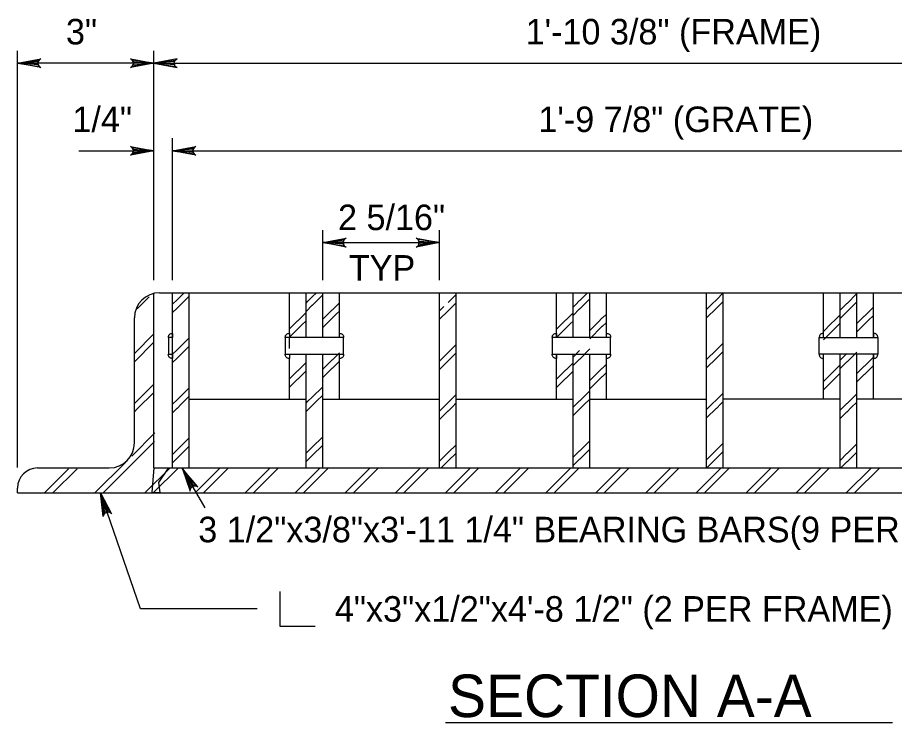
# Model space of a CAD drawing. Extents: x 0.71 to 8.05, y -5.67 to 4.31.
# Drawn here: x 0.92 to 2.981, y -1.711 to -0.055 of the extents above; entities that cross this region are included whole.
import ezdxf

# ---------------------------------------------------------------- set-up
doc = ezdxf.new("R2010")
doc.units = 0
for name, color, linetype in [('DETL-DIMS', 7, 'Continuous'), ('DETL-LINE', 7, 'Continuous'), ('DETL-NOTE', 7, 'Continuous'), ('DETL-PATT', 7, 'Continuous'), ('DETL-TITL', 7, 'Continuous')]:
    doc.layers.add(name, color=color, linetype=linetype)

msp = doc.modelspace()

# ---------------------------------------------------------------- linework, layer by layer
at = {"layer": 'DETL-DIMS'}
for p, q in [((0.9201, -1.1122), (0.9201, -0.1331)), ((1.2402, -0.6723), (1.2402, -0.1331)), ((1.2402, -0.1625), (0.9201, -0.1625)), ((1.2402, -0.1625), (3.8775, -0.1625)), ((1.2844, -0.6723), (1.2844, -0.339)), ((1.0638, -0.3684), (1.2402, -0.3684)), ((1.2844, -0.3684), (3.8334, -0.3684)), ((1.6373, -0.6723), (1.6373, -0.5547)), ((1.9118, -0.6723), (1.9118, -0.5547)), ((1.6373, -0.5841), (1.9118, -0.5841)), ((1.3608, -1.2069), (1.3075, -1.1153)), ((1.2087, -1.4447), (1.1148, -1.1723)), ((1.4828, -1.4447), (1.2087, -1.4447))]:
    msp.add_line(p, q, dxfattribs=at)
for points in [[(0.9201, -0.1625), (0.975, -0.1522), (0.9707, -0.1552), (0.9686, -0.1588), (0.9679, -0.1625), (0.9686, -0.1662), (0.9707, -0.1699), (0.975, -0.1728), (0.9201, -0.1625), (0.9707, -0.1699), (0.9686, -0.1662), (0.9201, -0.1625), (0.9679, -0.1625), (0.9686, -0.1588), (0.9201, -0.1625), (0.9707, -0.1552)], [(1.2402, -0.1625), (1.1854, -0.1728), (1.1896, -0.1699), (1.1918, -0.1662), (1.1924, -0.1625), (1.1918, -0.1588), (1.1896, -0.1552), (1.1854, -0.1522), (1.2402, -0.1625), (1.1896, -0.1552), (1.1918, -0.1588), (1.2402, -0.1625), (1.1924, -0.1625), (1.1918, -0.1662), (1.2402, -0.1625), (1.1896, -0.1699)], [(1.2402, -0.1625), (1.2951, -0.1728), (1.2908, -0.1699), (1.2887, -0.1662), (1.288, -0.1625), (1.2887, -0.1588), (1.2908, -0.1552), (1.2951, -0.1522), (1.2402, -0.1625), (1.2908, -0.1552), (1.2887, -0.1588), (1.2402, -0.1625), (1.288, -0.1625), (1.2887, -0.1662), (1.2402, -0.1625), (1.2908, -0.1699)], [(1.2402, -0.3684), (1.1854, -0.3787), (1.1896, -0.3758), (1.1918, -0.3721), (1.1924, -0.3684), (1.1918, -0.3647), (1.1896, -0.3611), (1.1854, -0.3581), (1.2402, -0.3684), (1.1896, -0.3611), (1.1918, -0.3647), (1.2402, -0.3684), (1.1924, -0.3684), (1.1918, -0.3721), (1.2402, -0.3684), (1.1896, -0.3758)], [(1.2844, -0.3684), (1.3392, -0.3581), (1.335, -0.3611), (1.3328, -0.3647), (1.3322, -0.3684), (1.3328, -0.3721), (1.335, -0.3758), (1.3392, -0.3787), (1.2844, -0.3684), (1.335, -0.3758), (1.3328, -0.3721), (1.2844, -0.3684), (1.3322, -0.3684), (1.3328, -0.3647), (1.2844, -0.3684), (1.335, -0.3611)], [(1.6373, -0.5841), (1.6921, -0.5738), (1.6879, -0.5767), (1.6857, -0.5804), (1.6851, -0.5841), (1.6857, -0.5878), (1.6879, -0.5914), (1.6921, -0.5944), (1.6373, -0.5841), (1.6879, -0.5914), (1.6857, -0.5878), (1.6373, -0.5841), (1.6851, -0.5841), (1.6857, -0.5804), (1.6373, -0.5841), (1.6879, -0.5767)], [(1.9118, -0.5841), (1.857, -0.5944), (1.8612, -0.5914), (1.8634, -0.5878), (1.864, -0.5841), (1.8634, -0.5804), (1.8612, -0.5767), (1.857, -0.5738), (1.9118, -0.5841), (1.8612, -0.5767), (1.8634, -0.5804), (1.9118, -0.5841), (1.864, -0.5841), (1.8634, -0.5878), (1.9118, -0.5841), (1.8612, -0.5914)], [(1.3075, -1.1153), (1.3257, -1.168), (1.3262, -1.1629), (1.3283, -1.1591), (1.3312, -1.1568), (1.3347, -1.1555), (1.3389, -1.1556), (1.3436, -1.1578), (1.3075, -1.1153), (1.3389, -1.1556), (1.3347, -1.1555), (1.3075, -1.1153), (1.3312, -1.1568), (1.3283, -1.1591), (1.3075, -1.1153), (1.3262, -1.1629)], [(1.1148, -1.1723), (1.1413, -1.2214), (1.1373, -1.2183), (1.1331, -1.2173), (1.1294, -1.2178), (1.1261, -1.2196), (1.1232, -1.2228), (1.1217, -1.2277), (1.1148, -1.1723), (1.1232, -1.2228), (1.1261, -1.2196), (1.1148, -1.1723), (1.1294, -1.2178), (1.1331, -1.2173), (1.1148, -1.1723), (1.1373, -1.2183)]]:
    msp.add_lwpolyline(points, dxfattribs=at)
at = {"layer": 'DETL-LINE'}
for p, q in [((1.2402, -1.1135), (1.2402, -0.7017)), ((1.2535, -0.7017), (3.8643, -0.7017)), ((1.2844, -1.1135), (1.2844, -0.7017)), ((1.3236, -1.1135), (1.3236, -0.7017)), ((1.5589, -0.7974), (1.5589, -0.7017)), ((1.5981, -0.8071), (1.5981, -0.7017)), ((1.6373, -0.8071), (1.6373, -0.7017)), ((1.6765, -0.7971), (1.6765, -0.7017)), ((1.9118, -1.1135), (1.9118, -0.7017)), ((1.951, -1.1135), (1.951, -0.7017)), ((2.1863, -0.8071), (2.1863, -0.7017)), ((2.2255, -0.8071), (2.2255, -0.7017)), ((2.2648, -0.8071), (2.2648, -0.7017)), ((2.304, -0.8071), (2.304, -0.7017)), ((2.5393, -1.1135), (2.5393, -0.7017)), ((2.5785, -1.1135), (2.5785, -0.7017)), ((2.8138, -0.8071), (2.8138, -0.7017)), ((2.853, -0.8071), (2.853, -0.7017)), ((2.8922, -0.8071), (2.8922, -0.7017)), ((2.9314, -0.8071), (2.9314, -0.7017)), ((1.1947, -1.0547), (1.1947, -0.7606)), ((1.5589, -0.8326), (1.5589, -0.8071)), ((1.5589, -0.9517), (1.5589, -0.8562)), ((1.5981, -1.1135), (1.5981, -0.8463)), ((1.6373, -1.1135), (1.6373, -0.8463)), ((1.6765, -0.9517), (1.6765, -0.8561)), ((2.1863, -0.9517), (2.1863, -0.8463)), ((2.2255, -1.1135), (2.2255, -0.8463)), ((2.2648, -1.1135), (2.2648, -0.8463)), ((2.304, -0.9517), (2.304, -0.8463)), ((2.8138, -0.9517), (2.8138, -0.8463)), ((2.853, -1.1135), (2.853, -0.8463)), ((2.8922, -1.1135), (2.8922, -0.8463)), ((2.9314, -0.9517), (2.9314, -0.8463)), ((1.3236, -0.9517), (1.5981, -0.9517)), ((1.6373, -0.9517), (1.9118, -0.9517)), ((1.951, -0.9517), (2.2255, -0.9517)), ((2.2648, -0.9517), (2.5393, -0.9517)), ((2.853, -0.9517), (2.5785, -0.9517)), ((3.1667, -0.9517), (2.8922, -0.9517)), ((0.9672, -1.1135), (1.1358, -1.1135)), ((1.2402, -1.1135), (3.8775, -1.1135)), ((0.9201, -1.1723), (0.9201, -1.1606)), ((0.9201, -1.1723), (3.9819, -1.1723))]:
    msp.add_line(p, q, dxfattribs=at)
for points in [[(1.2745, -0.8071), (1.2745, -0.8054), (1.2748, -0.8037), (1.2753, -0.8024), (1.2758, -0.8014), (1.2766, -0.8004), (1.2774, -0.7996), (1.2788, -0.7986), (1.2805, -0.7977), (1.2818, -0.7974), (1.2831, -0.7972), (1.2843, -0.7973), (1.2843, -0.8071)], [(1.5491, -0.8071), (1.5491, -0.8055), (1.5494, -0.8037), (1.5499, -0.8024), (1.5505, -0.8015), (1.5512, -0.8005), (1.552, -0.7996), (1.5534, -0.7986), (1.5551, -0.7978), (1.5564, -0.7975), (1.5577, -0.7973), (1.5589, -0.7974), (1.5589, -0.8071)], [(1.6765, -0.7973), (1.6782, -0.7974), (1.6799, -0.7977), (1.6812, -0.7982), (1.6822, -0.7987), (1.6832, -0.7995), (1.684, -0.8003), (1.685, -0.8017), (1.6859, -0.8033), (1.6862, -0.8047), (1.6864, -0.806), (1.6863, -0.8071), (1.6765, -0.8071)], [(2.1765, -0.8071), (2.1766, -0.8055), (2.1768, -0.8037), (2.1774, -0.8024), (2.1779, -0.8015), (2.1787, -0.8005), (2.1795, -0.7996), (2.1808, -0.7986), (2.1825, -0.7978), (2.1839, -0.7975), (2.1852, -0.7973), (2.1863, -0.7974), (2.1863, -0.8071)], [(2.304, -0.7973), (2.3056, -0.7974), (2.3074, -0.7977), (2.3087, -0.7982), (2.3096, -0.7987), (2.3106, -0.7995), (2.3115, -0.8003), (2.3125, -0.8017), (2.3133, -0.8033), (2.3136, -0.8047), (2.3138, -0.806), (2.3137, -0.8071), (2.304, -0.8071)], [(2.8138, -0.7973), (2.8121, -0.7974), (2.8104, -0.7977), (2.8091, -0.7982), (2.8081, -0.7987), (2.8071, -0.7995), (2.8063, -0.8003), (2.8053, -0.8017), (2.8044, -0.8033), (2.8041, -0.8047), (2.8039, -0.806), (2.804, -0.8071), (2.8138, -0.8071)], [(2.9412, -0.8071), (2.9412, -0.8055), (2.9409, -0.8037), (2.9404, -0.8024), (2.9398, -0.8015), (2.939, -0.8005), (2.9383, -0.7996), (2.9369, -0.7986), (2.9352, -0.7978), (2.9339, -0.7975), (2.9326, -0.7973), (2.9314, -0.7974), (2.9314, -0.8071)], [(1.2745, -0.8463), (1.2843, -0.8463), (1.2843, -0.8071), (1.2745, -0.8071)], [(1.5491, -0.8463), (1.6863, -0.8463), (1.6863, -0.8071), (1.5491, -0.8071)], [(2.1766, -0.8463), (2.3137, -0.8463), (2.3137, -0.8071), (2.1766, -0.8071)], [(2.9412, -0.8463), (2.804, -0.8463), (2.804, -0.8071), (2.9412, -0.8071)], [(1.2843, -0.8561), (1.2826, -0.8561), (1.2809, -0.8558), (1.2796, -0.8552), (1.2786, -0.8547), (1.2776, -0.8539), (1.2768, -0.8532), (1.2758, -0.8518), (1.2749, -0.8501), (1.2746, -0.8487), (1.2744, -0.8474), (1.2745, -0.8463), (1.2843, -0.8463)], [(1.5589, -0.8562), (1.5572, -0.8561), (1.5555, -0.8558), (1.5542, -0.8553), (1.5532, -0.8548), (1.5522, -0.854), (1.5514, -0.8532), (1.5504, -0.8518), (1.5495, -0.8501), (1.5492, -0.8488), (1.549, -0.8475), (1.5491, -0.8463), (1.5589, -0.8463)], [(1.6863, -0.8463), (1.6863, -0.848), (1.686, -0.8497), (1.6855, -0.8511), (1.6849, -0.852), (1.6841, -0.853), (1.6834, -0.8538), (1.682, -0.8549), (1.6803, -0.8557), (1.6789, -0.856), (1.6777, -0.8562), (1.6765, -0.8561), (1.6765, -0.8463)], [(2.1863, -0.8562), (2.1847, -0.8561), (2.1829, -0.8558), (2.1816, -0.8553), (2.1807, -0.8548), (2.1797, -0.854), (2.1788, -0.8532), (2.1778, -0.8518), (2.177, -0.8501), (2.1767, -0.8488), (2.1765, -0.8475), (2.1766, -0.8463), (2.1863, -0.8463)], [(2.3138, -0.8463), (2.3137, -0.848), (2.3134, -0.8497), (2.3129, -0.8511), (2.3124, -0.852), (2.3116, -0.853), (2.3108, -0.8538), (2.3094, -0.8549), (2.3078, -0.8557), (2.3064, -0.856), (2.3051, -0.8562), (2.304, -0.8561), (2.304, -0.8463)], [(2.804, -0.8463), (2.804, -0.848), (2.8043, -0.8497), (2.8048, -0.8511), (2.8054, -0.852), (2.8062, -0.853), (2.8069, -0.8538), (2.8083, -0.8549), (2.81, -0.8557), (2.8113, -0.856), (2.8126, -0.8562), (2.8138, -0.8561), (2.8138, -0.8463)], [(2.9314, -0.8562), (2.9331, -0.8561), (2.9348, -0.8558), (2.9361, -0.8553), (2.9371, -0.8548), (2.9381, -0.854), (2.9389, -0.8532), (2.9399, -0.8518), (2.9408, -0.8501), (2.9411, -0.8488), (2.9413, -0.8475), (2.9412, -0.8463), (2.9314, -0.8463)], [(1.2402, -1.1135), (1.2357, -1.1713), (1.2551, -1.1713), (1.2525, -1.1473), (1.2745, -1.1141)]]:
    msp.add_lwpolyline(points, close=True, dxfattribs=at)
for centre, radius, start, end in [((1.2535, -0.7606), 0.0588, 90, 180), ((1.1358, -1.0547), 0.0588, 270, 0), ((0.9672, -1.1606), 0.0471, 90, 180)]:
    msp.add_arc(centre, radius, start, end, dxfattribs=at)
at = {"layer": 'DETL-NOTE'}
for p, q in [((1.5373, -1.486), (1.5373, -1.4037)), ((1.6197, -1.486), (1.5373, -1.486))]:
    msp.add_line(p, q, dxfattribs=at)
at = {"layer": 'DETL-PATT'}
for p, q in [((1.2013, -0.7396), (1.2295, -0.7113)), ((1.2852, -0.728), (1.295, -0.7182)), ((1.2954, -0.7182), (1.3118, -0.7017)), ((1.3052, -0.728), (1.3236, -0.7096)), ((1.6025, -0.7215), (1.6123, -0.7117)), ((1.6128, -0.7117), (1.6228, -0.7017)), ((1.6226, -0.7215), (1.6373, -0.7068)), ((1.9323, -0.7246), (1.951, -0.7058)), ((2.2308, -0.7301), (2.2406, -0.7203)), ((2.2411, -0.7203), (2.2596, -0.7017)), ((2.2509, -0.7301), (2.2648, -0.7162)), ((2.5525, -0.728), (2.5623, -0.7182)), ((2.5627, -0.7182), (2.5785, -0.7024)), ((2.8693, -0.7267), (2.8922, -0.7039)), ((1.2844, -0.7484), (1.295, -0.7378)), ((1.3052, -0.728), (1.295, -0.7382)), ((1.5981, -0.726), (1.6025, -0.7215)), ((1.5981, -0.7456), (1.6123, -0.7313)), ((1.6226, -0.7215), (1.6123, -0.7318)), ((1.6497, -0.7516), (1.6595, -0.7418)), ((1.66, -0.7418), (1.6765, -0.7252)), ((1.9118, -0.7446), (1.922, -0.7344)), ((1.9421, -0.7344), (1.9318, -0.7446)), ((1.9421, -0.7344), (1.951, -0.7254)), ((2.2255, -0.7354), (2.2308, -0.7301)), ((2.2255, -0.755), (2.2406, -0.7399)), ((2.2509, -0.7301), (2.2406, -0.7403)), ((2.5393, -0.7412), (2.5525, -0.728)), ((2.5393, -0.7608), (2.5623, -0.7378)), ((2.5725, -0.728), (2.5623, -0.7382)), ((2.5725, -0.728), (2.5785, -0.722)), ((2.853, -0.7427), (2.8591, -0.7365)), ((2.8591, -0.7365), (2.8689, -0.7267)), ((2.8791, -0.7365), (2.8689, -0.7468)), ((2.8791, -0.7365), (2.8922, -0.7235)), ((2.9101, -0.7568), (2.9314, -0.7354)), ((1.5785, -0.7675), (1.5981, -0.7479)), ((1.6373, -0.764), (1.6497, -0.7516)), ((1.6373, -0.7836), (1.6595, -0.7614)), ((1.6698, -0.7516), (1.6595, -0.7618)), ((1.6698, -0.7516), (1.6765, -0.7448)), ((1.9118, -0.7642), (1.9318, -0.7442)), ((2.2089, -0.7654), (2.2255, -0.7487)), ((2.2844, -0.7709), (2.2942, -0.7611)), ((2.2947, -0.7611), (2.304, -0.7518)), ((2.8415, -0.7654), (2.853, -0.7538)), ((2.853, -0.7623), (2.8689, -0.7463)), ((2.8999, -0.7666), (2.9097, -0.7568)), ((2.9199, -0.7666), (2.9314, -0.755)), ((1.5589, -0.7867), (1.5682, -0.7773)), ((1.5682, -0.7773), (1.578, -0.7675)), ((1.5883, -0.7773), (1.578, -0.7875)), ((1.5883, -0.7773), (1.5981, -0.7675)), ((2.1863, -0.7875), (2.1987, -0.7752)), ((2.1987, -0.7752), (2.2085, -0.7654)), ((2.2187, -0.7752), (2.2085, -0.7854)), ((2.2187, -0.7752), (2.2255, -0.7683)), ((2.2648, -0.7905), (2.2844, -0.7709)), ((2.2648, -0.8102), (2.2942, -0.7807)), ((2.304, -0.7714), (2.2942, -0.7811)), ((2.8138, -0.7926), (2.8312, -0.7752)), ((2.8312, -0.7752), (2.841, -0.7654)), ((2.8513, -0.7752), (2.841, -0.7854)), ((2.8922, -0.7742), (2.8999, -0.7666)), ((2.8922, -0.7938), (2.9097, -0.7764)), ((2.9199, -0.7666), (2.9097, -0.7768)), ((1.1947, -0.8443), (1.2402, -0.7987)), ((1.5589, -0.8063), (1.578, -0.7871)), ((2.1863, -0.8071), (2.2085, -0.785)), ((2.8138, -0.8122), (2.841, -0.785)), ((1.1947, -0.8639), (1.2402, -0.8183)), ((1.2954, -0.8358), (1.3236, -0.8076)), ((1.9323, -0.8422), (1.951, -0.8235)), ((2.5627, -0.8358), (2.5785, -0.82)), ((1.2844, -0.8464), (1.295, -0.8358)), ((1.3236, -0.8272), (1.2954, -0.8554)), ((1.66, -0.8594), (1.6765, -0.8428)), ((1.9118, -0.8623), (1.9318, -0.8422)), ((1.951, -0.8431), (1.9323, -0.8618)), ((2.2255, -0.853), (2.2406, -0.8379)), ((2.2648, -0.8339), (2.2411, -0.8576)), ((2.5393, -0.8588), (2.5623, -0.8358)), ((2.5785, -0.8396), (2.5627, -0.8554)), ((2.853, -0.8603), (2.8689, -0.8444)), ((2.8922, -0.8411), (2.8693, -0.864)), ((1.2844, -0.866), (1.295, -0.8554)), ((1.6373, -0.8816), (1.6595, -0.8594)), ((1.6765, -0.8624), (1.66, -0.879)), ((1.9118, -0.8819), (1.9318, -0.8618)), ((2.2255, -0.8726), (2.2406, -0.8576)), ((2.5393, -0.8784), (2.5623, -0.8554)), ((2.853, -0.8799), (2.8689, -0.864)), ((2.9101, -0.8744), (2.9314, -0.8531)), ((1.5589, -0.9043), (1.578, -0.8851)), ((1.5785, -0.8851), (1.5981, -0.8655)), ((1.5981, -0.8851), (1.5785, -0.9048)), ((1.6373, -0.9012), (1.6595, -0.879)), ((2.1863, -0.9051), (2.2085, -0.883)), ((2.2089, -0.883), (2.2255, -0.8664)), ((2.2255, -0.886), (2.2089, -0.9026)), ((2.2648, -0.9082), (2.2942, -0.8787)), ((2.2947, -0.8787), (2.304, -0.8694)), ((2.8138, -0.9103), (2.841, -0.883)), ((2.8415, -0.883), (2.853, -0.8715)), ((2.8922, -0.8919), (2.9097, -0.8744)), ((2.9314, -0.8727), (2.9101, -0.894)), ((1.5589, -0.9239), (1.578, -0.9048)), ((2.1863, -0.9247), (2.2085, -0.9026)), ((2.2648, -0.9278), (2.2942, -0.8983)), ((2.304, -0.889), (2.2947, -0.8983)), ((2.8138, -0.9299), (2.841, -0.9026)), ((2.853, -0.8911), (2.8415, -0.9026)), ((2.8922, -0.9115), (2.9097, -0.894)), ((1.1947, -0.9619), (1.2402, -0.9163)), ((1.2954, -0.9534), (1.3236, -0.9253)), ((1.6128, -0.947), (1.6373, -0.9225)), ((1.2013, -0.9749), (1.2402, -0.9359)), ((1.3052, -0.9632), (1.3236, -0.9449)), ((1.6025, -0.9568), (1.6123, -0.947)), ((1.6226, -0.9568), (1.6373, -0.9421)), ((1.9323, -0.9599), (1.951, -0.9411)), ((2.2411, -0.9556), (2.2648, -0.9319)), ((2.5627, -0.9534), (2.5785, -0.9377)), ((2.8693, -0.962), (2.8922, -0.9392)), ((1.2852, -0.9632), (1.295, -0.9534)), ((1.3052, -0.9632), (1.295, -0.9735)), ((1.5981, -0.9613), (1.6025, -0.9568)), ((1.5981, -0.9809), (1.6123, -0.9666)), ((1.6226, -0.9568), (1.6123, -0.967)), ((1.922, -0.9697), (1.9318, -0.9599)), ((1.9421, -0.9697), (1.951, -0.9607)), ((2.2255, -0.9707), (2.2308, -0.9654)), ((2.2308, -0.9654), (2.2406, -0.9556)), ((2.2509, -0.9654), (2.2406, -0.9756)), ((2.2509, -0.9654), (2.2648, -0.9515)), ((2.5393, -0.9765), (2.5525, -0.9632)), ((2.5525, -0.9632), (2.5623, -0.9534)), ((2.5725, -0.9632), (2.5623, -0.9735)), ((2.5725, -0.9632), (2.5785, -0.9573)), ((2.8591, -0.9718), (2.8689, -0.962)), ((2.8791, -0.9718), (2.8922, -0.9588)), ((1.2013, -0.9749), (1.1947, -0.9815)), ((1.2844, -0.9837), (1.295, -0.9731)), ((1.9118, -0.9799), (1.922, -0.9697)), ((1.9118, -0.9995), (1.9318, -0.9795)), ((1.9421, -0.9697), (1.9318, -0.9799)), ((2.2255, -0.9903), (2.2406, -0.9752)), ((2.5393, -0.9961), (2.5623, -0.9731)), ((2.853, -0.978), (2.8591, -0.9718)), ((2.853, -0.9976), (2.8689, -0.9816)), ((2.8791, -0.9718), (2.8689, -0.9821)), ((1.1888, -1.0855), (1.2429, -1.0313)), ((1.2954, -1.0711), (1.3236, -1.0429)), ((1.6128, -1.0647), (1.6373, -1.0401)), ((2.2411, -1.0732), (2.2648, -1.0495)), ((1.1215, -1.1723), (1.2422, -1.0516)), ((1.2844, -1.0817), (1.295, -1.0711)), ((1.3236, -1.0625), (1.2954, -1.0907)), ((1.5981, -1.0789), (1.6123, -1.0647)), ((1.6373, -1.0597), (1.6128, -1.0843)), ((1.9323, -1.0775), (1.951, -1.0588)), ((2.2648, -1.0692), (2.2411, -1.0928)), ((2.5393, -1.0941), (2.5623, -1.0711)), ((2.5627, -1.0711), (2.5785, -1.0553)), ((2.8693, -1.0797), (2.8922, -1.0568)), ((1.2844, -1.1013), (1.295, -1.0907)), ((1.5981, -1.0985), (1.6123, -1.0843)), ((1.9118, -1.0976), (1.9318, -1.0775)), ((1.951, -1.0784), (1.9323, -1.0971)), ((2.2255, -1.0883), (2.2406, -1.0732)), ((2.5395, -1.1135), (2.5623, -1.0907)), ((2.5785, -1.0749), (2.5627, -1.0907)), ((2.853, -1.0956), (2.8689, -1.0797)), ((2.8922, -1.0764), (2.8693, -1.0993)), ((1.1019, -1.1723), (1.1739, -1.1003)), ((1.9155, -1.1135), (1.9318, -1.0971)), ((2.2255, -1.1079), (2.2406, -1.0928)), ((2.8547, -1.1135), (2.8689, -1.0993)), ((0.9838, -1.1723), (1.0402, -1.1159)), ((1.0034, -1.1723), (1.0603, -1.1154)), ((1.2195, -1.1723), (1.2784, -1.1135)), ((1.2391, -1.1723), (1.298, -1.1135)), ((1.3372, -1.1723), (1.396, -1.1135)), ((1.3568, -1.1723), (1.4156, -1.1135)), ((1.4548, -1.1723), (1.5136, -1.1135)), ((1.4744, -1.1723), (1.5333, -1.1135)), ((1.5725, -1.1723), (1.6313, -1.1135)), ((1.5921, -1.1723), (1.6509, -1.1135)), ((1.6901, -1.1723), (1.7489, -1.1135)), ((1.7097, -1.1723), (1.7686, -1.1135)), ((1.8082, -1.1723), (1.867, -1.1135)), ((1.8278, -1.1723), (1.8866, -1.1135)), ((1.9258, -1.1723), (1.9847, -1.1135)), ((1.9455, -1.1723), (2.0043, -1.1135)), ((2.0435, -1.1723), (2.1023, -1.1135)), ((2.0631, -1.1723), (2.1219, -1.1135)), ((2.1611, -1.1723), (2.22, -1.1135)), ((2.1807, -1.1723), (2.2396, -1.1135)), ((2.2788, -1.1723), (2.3376, -1.1135)), ((2.2984, -1.1723), (2.3572, -1.1135)), ((2.3964, -1.1723), (2.4553, -1.1135)), ((2.416, -1.1723), (2.4749, -1.1135)), ((2.5145, -1.1723), (2.5733, -1.1135)), ((2.5341, -1.1723), (2.5929, -1.1135)), ((2.6322, -1.1723), (2.691, -1.1135)), ((2.6518, -1.1723), (2.7106, -1.1135)), ((2.7498, -1.1723), (2.8086, -1.1135)), ((2.7694, -1.1723), (2.8282, -1.1135)), ((2.8675, -1.1723), (2.9263, -1.1135)), ((2.8871, -1.1723), (2.9459, -1.1135))]:
    msp.add_line(p, q, dxfattribs=at)
at = {"layer": 'DETL-TITL'}
msp.add_line((1.9259, -1.7114), (2.9761, -1.7114), dxfattribs=at)

# ---------------------------------------------------------------- texts
at = {"layer": 'DETL-NOTE'}
for s, p in [('3"', (1.0339, -0.1184)), ('1\'-10 3/8" (FRAME)', (2.1139, -0.1184)), ('1/4"', (1.0491, -0.3243)), ('1\'-9 7/8" (GRATE)', (2.1439, -0.3243)), ('2 5/16"', (1.6732, -0.5547)), ('TYP', (1.6986, -0.6735)), ('3 1/2"x3/8"x3\'-11 1/4" BEARING BARS(9 PER GRATE)', (1.3448, -1.2881)), ('4"x3"x1/2"x4\'-8 1/2" (2 PER FRAME)', (1.6658, -1.4747))]:
    msp.add_text(s, height=0.06, dxfattribs=at).set_placement(p)
at = {"layer": 'DETL-TITL'}
msp.add_text('SECTION A-A', height=0.1, dxfattribs=at).set_placement((1.9317, -1.6988))

doc.saveas('drawing.dxf')
